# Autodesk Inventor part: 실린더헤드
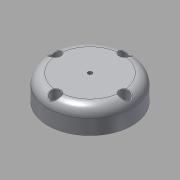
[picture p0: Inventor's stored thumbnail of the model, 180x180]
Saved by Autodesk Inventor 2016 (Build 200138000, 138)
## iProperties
Created: 2016-11
Part Number: 실린더헤드
Material: 알루미늄 6061
Document SubType Name: Modeling
Designer: mduedu
Density: 2.71 g/cm^3
Mass: 284.827 g
Surface Area: 227.25 cm^2
Volume: 105.102 cm^3
Appearance: 알루미늄 - 평지
Author: mduedu
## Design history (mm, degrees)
sketch "스케치1"
  geometry: C1 r 42.5 at (0, 0); 1 further point
  constraints: 1 centre point, 1 coincident
  dimensions: "d0" = 85 diameter of C1
extrude "돌출1" new body sketch "스케치1" distance "d1" = 25; taper "d2" = 0 deg
fillet "모깎기1" dims "d3" = 10
sketch "스케치2"
  geometry: C1 r 30 at (0, 0); 1 further point
  constraints: 1 centre point, 1 coincident
  dimensions: "d4" = 60 diameter of C1
extrude "돌출2" join sketch "스케치2" distance "d5" = 5; taper "d6" = 0 deg
sketch "스케치3"
  geometry: C1 r 25 at (0, 0); 1 further point
  constraints: 1 centre point, 1 coincident
  dimensions: "d7" = 50 diameter of C1
extrude "돌출3" cut sketch "스케치3" distance "d8" = 20; taper "d9" = 0 deg
hole "구멍1" diameter "d12" = 4.134; stored, may be unused: countersink angle "d16" = 90 deg, drill point angle "d18" = 118 deg; dims "d10" = 10, "d11" = 10, "d13" = 6, "d14" = 4, "d15" = 2, "d17" = 8
chamfer "모따기1" distance "d19" = 1; stored, may be unused: second distance "d20" = 2, angle "d21" = 45 deg
fillet "모깎기2" dims "d22" = 3
sketch "스케치4"
  geometry: C1 r 17.5 at (0, 0); 1 further point
  constraints: 1 centre point, 1 coincident
  dimensions: "d23" = 35 diameter of C1
extrude "돌출4" cut sketch "스케치4" distance "d24" = 2; taper "d25" = 0 deg
fillet "모깎기3" dims "d26" = 0.5
sketch "스케치5" dims "d32" = 70
  geometry: C1 r 5 at (0, 35); 3 further points
  constraints: 2 coincident, 2 vertical alignment, 1 centre point, 2 other
  dimensions: "d33" = 10 diameter of C1
extrude "돌출5" cut sketch "스케치5" distance "d34" = 10; taper "d35" = 0 deg
sketch "스케치6" dims "d39" = 70
  geometry: 6 further points
  constraints: 2 vertical alignment, 1 coincident, 7 other
  dimensions: "d42" = 360 deg dimension on point (0, -35) point (0, 0) (derived)
sketch "스케치7"
  geometry: 4 further points
  constraints: 4 other
hole "구멍2" sketch "스케치7" at (0, 70), (-35, 35), (35, 35), (0, 0) diameter "d44" = 5.5; stored, may be unused: countersink angle "d48" = 90 deg, drill point angle "d50" = 0 deg; dims "d45" = 6, "d46" = 4, "d47" = 2, "d49" = 8
fillet "모깎기4" dims "d51" = 0.5
node "솔리드1"
pattern_circular "원형 패턴1" dims angle "d37" = 360 deg
